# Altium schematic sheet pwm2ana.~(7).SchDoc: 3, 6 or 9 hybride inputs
size A4; Revision: V0.1; SheetNumber: 1; SheetTotal: 1; PageSetup: Record=PageOptions¦CenterHorizontal=True¦CenterVertical=True¦PrintScale=1.00¦XCorrection=1.00¦YCorrection=1.00¦PrintKind=2¦BorderSize=5000000¦LeftOffset=0¦BottomOffset=0¦Orientation=2¦PaperLength=1000¦PaperWidth=1000¦Scale=100¦PaperSource=7¦PrintQuality=-4¦MediaType=1¦DitherType=10¦PaperKind=A4¦PrintScaleMode=1
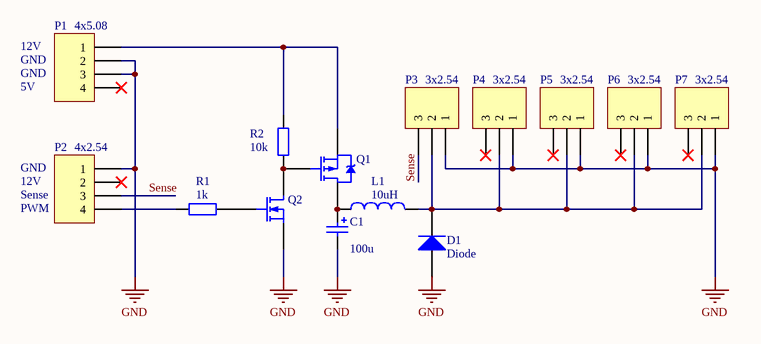
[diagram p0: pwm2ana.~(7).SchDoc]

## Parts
C1  100u  [POLAR0.8]
D1  Diode  [SMC]
L1  10uH  [0402-A]
P1  4x5.08  [HDR1X4]
P2  4x2.54  [HDR1X4]
P3  3x2.54  [HDR1X3]
P4  3x2.54  [HDR1X3]
P5  3x2.54  [HDR1X3]
P6  3x2.54  [HDR1X3]
P7  3x2.54  [HDR1X3]
Q1  PMOS-2  [TO-220AB]  (value not drawn)
Q2  MOSFET-N  [E3]  (value not drawn)
R1  1k  [R0805]
R2  10k  [R0805]

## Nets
GND: C1.2 D1.1(A) P1.2 P1.3 P2.1 P3.1 P4.1 P5.1 P6.1 P7.1 Q2.3(S)
Sense: P2.3 P3.3
NetC1_1: C1.1 L1.1 Q1.2(D)
NetD1_2: D1.2(K) L1.2 P3.2 P4.2 P5.2 P6.2 P7.2
NetP1_1: P1.1 Q1.3(S) R2.1
NetP2_4: P2.4 R1.1
NetQ1_1: Q1.1(G) Q2.1(D) R2.2
NetQ2_2: Q2.2(G) R1.2

Not connected (* = marked no-connect by the designer): P1 4*; P2 2*; P4 3*; P5 3*; P6 3*; P7 3*

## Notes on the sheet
- GND
- 12V
- 5V
- (near P2) Sense
- PWM

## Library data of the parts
C1 = Cap Pol2: Polarized Capacitor (Axial)
D1 = Diode: Default Diode
L1 = Inductor: Code_IEC: 1005
P1 P2 = Header 4: Header, 4-Pin
P3-P7 = Header 3: Header, 3-Pin
Q1 = PMOS-2: P-Channel Power MOSFET; Note: Pin 4 not drawn and electrically connected to Pin 2.
Q2 = MOSFET-N: N-Channel MOSFET
R1 R2 = Res2: Resistor; Manufacturer: MULTICOMP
